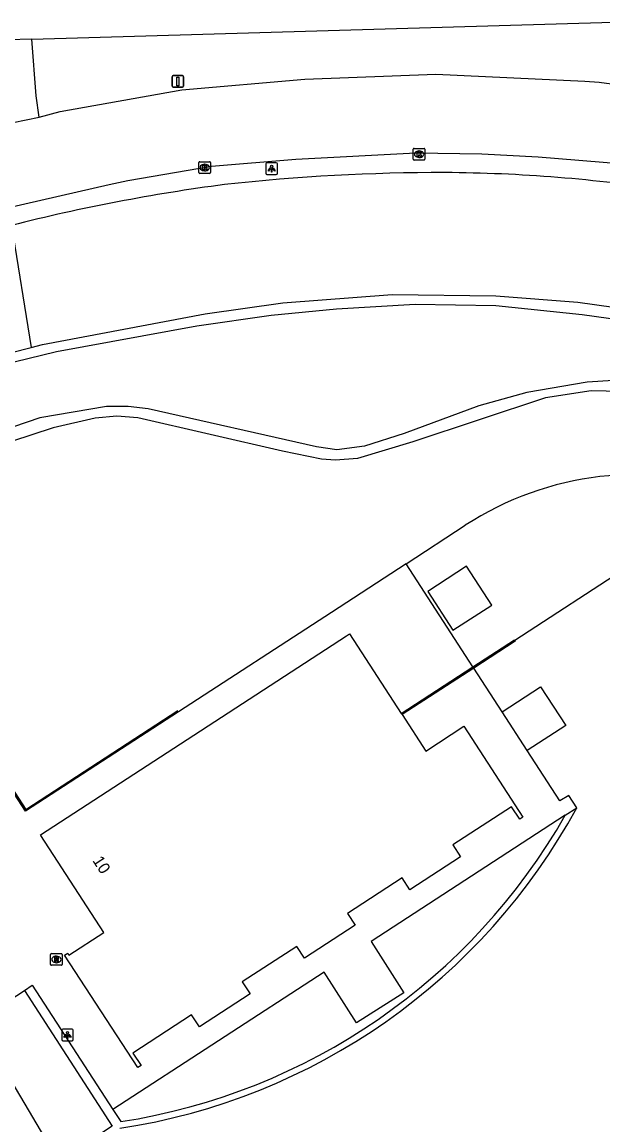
# Model space of a CAD drawing. Extents: x 159451 to 160663, y 388402 to 389723.
# Drawn here: x 160044.7 to 160094.7, y 389283.8 to 389378.7 of the extents above; entities that cross this region are included whole.
import ezdxf

# ---------------------------------------------------------------- set-up
doc = ezdxf.new("R2010")
doc.units = 0
for name, color, linetype in [('IMGEO_Berm_groen', 7, 'Continuous'), ('IMGEO_Groenvoorziening', 7, 'Continuous'), ('IMGEO_Haag', 7, 'Continuous'), ('IMGEO_Kolk', 7, 'Continuous'), ('IMGEO_Lichtpunt', 7, 'Continuous'), ('IMGEO_Loofbos', 7, 'Continuous'), ('IMGEO_Meer_plas_ven_vijver', 7, 'Continuous'), ('IMGEO_Muur', 7, 'Continuous'), ('IMGEO_Open_loods', 7, 'Continuous'), ('IMGEO_Pand', 7, 'Continuous'), ('IMGEO_Pand_nummerreeks', 7, 'Continuous'), ('IMGEO_Parkeervlak_open', 7, 'Continuous'), ('IMGEO_Rijbaan_lokaal_gesloten', 7, 'Continuous'), ('IMGEO_Rijbaan_lokaal_open', 7, 'Continuous'), ('IMGEO_Rioolput', 7, 'Continuous'), ('IMGEO_Verkeersbordpaal', 7, 'Continuous'), ('IMGEO_Voetpad_open', 7, 'Continuous')]:
    doc.layers.add(name, color=color, linetype=linetype)

msp = doc.modelspace()

# ---------------------------------------------------------------- linework, layer by layer
at = {"layer": 'IMGEO_Berm_groen'}
for points in [[(160043.814, 389361.181), (160045.506, 389350.697)], [(160018.398, 389340.073), (160022.188, 389342.228), (160026.213, 389344.023), (160033.578, 389347.076), (160040.631, 389349.447), (160045.506, 389350.697)]]:
    msp.add_lwpolyline(points, dxfattribs=at)
at = {"layer": 'IMGEO_Groenvoorziening'}
for points in [[(160045.569, 389377.185), (160095.565, 389378.647), (160130.286, 389372.303), (160147.497, 389362.17), (160157.284, 389356.446), (160160.932, 389357.287)], [(160045.506, 389350.697), (160046.472, 389350.945), (160060.477, 389353.565), (160067.144, 389354.512), (160076.551, 389355.226), (160085.488, 389355.117), (160092.549, 389354.568), (160100.295, 389353.487), (160106.524, 389352.351), (160119.77, 389349.046), (160128.496, 389345.996), (160138.333, 389341.838), (160146.634, 389337.264), (160151.806, 389333.778), (160161.693, 389326.541), (160174.127, 389316.332), (160188.045, 389305.739), (160195.541, 389299.578), (160199.998, 389295.525), (160201.333, 389293.979), (160202.925, 389291.679)]]:
    msp.add_lwpolyline(points, dxfattribs=at)
at = {"layer": 'IMGEO_Haag'}
msp.add_lwpolyline([(160052.541, 389285.175), (160053.218, 389284.133)], dxfattribs=at)
for centre, radius, start, end in [((160045.066, 389336.905), 53.948, 278.60377, 331.43561), ((160045.068, 389336.904), 53.397, 278.77981, 330.32455)]:
    msp.add_arc(centre, radius, start, end, dxfattribs=at)
at = {"layer": 'IMGEO_Kolk'}
for p, q in [((160078.38, 389366.875), (160078.38, 389367.727)), ((160078.455, 389367.801), (160079.307, 389367.801)), ((160078.868, 389367.581), (160078.893, 389367.581)), ((160079.381, 389367.727), (160079.381, 389366.875)), ((160059.935, 389365.728), (160059.935, 389366.58)), ((160060.01, 389366.654), (160060.862, 389366.654)), ((160060.423, 389366.434), (160060.448, 389366.434)), ((160060.936, 389366.58), (160060.936, 389365.728)), ((160079.307, 389366.801), (160078.455, 389366.801)), ((160078.891, 389367.021), (160078.866, 389367.021)), ((160060.862, 389365.654), (160060.01, 389365.654)), ((160060.446, 389365.874), (160060.421, 389365.874))]:
    msp.add_line(p, q, dxfattribs=at)
for points in [[(160078.38, 389366.875), (160078.38, 389367.727)], [(160078.455, 389367.801), (160079.307, 389367.801)], [(160078.701, 389367.501), (160078.824, 389367.501), (160078.824, 389367.35), (160078.954, 389367.501), (160079.118, 389367.501), (160078.972, 389367.35), (160079.125, 389367.101), (160078.973, 389367.101), (160078.888, 389367.265), (160078.824, 389367.198), (160078.824, 389367.101), (160078.701, 389367.101), (160078.701, 389367.501)], [(160079.381, 389367.727), (160079.381, 389366.875)], [(160059.935, 389365.728), (160059.935, 389366.58)], [(160060.01, 389366.654), (160060.862, 389366.654)], [(160060.256, 389366.354), (160060.379, 389366.354), (160060.379, 389366.203), (160060.509, 389366.354), (160060.673, 389366.354), (160060.527, 389366.203), (160060.68, 389365.954), (160060.528, 389365.954), (160060.443, 389366.118), (160060.379, 389366.051), (160060.379, 389365.954), (160060.256, 389365.954), (160060.256, 389366.354)], [(160060.936, 389366.58), (160060.936, 389365.728)], [(160079.307, 389366.801), (160078.455, 389366.801)], [(160060.862, 389365.654), (160060.01, 389365.654)]]:
    msp.add_lwpolyline(points, dxfattribs=at)
for centre, start, end in [((160078.457, 389367.725), 91.55205, 178.44795), ((160078.457, 389367.725), 91.55205, 178.44795), ((160079.305, 389367.725), 1.55205, 88.44795), ((160079.305, 389367.725), 1.55205, 88.44795), ((160060.012, 389366.578), 91.55205, 178.44795), ((160060.012, 389366.578), 91.55205, 178.44795), ((160060.86, 389366.578), 1.55205, 88.44795), ((160060.86, 389366.578), 1.55205, 88.44795), ((160078.457, 389366.877), 181.55205, 268.44795), ((160078.457, 389366.877), 181.55205, 268.44795), ((160079.305, 389366.877), 271.55205, 358.44795), ((160079.305, 389366.877), 271.55205, 358.44795), ((160060.012, 389365.73), 181.55205, 268.44795), ((160060.012, 389365.73), 181.55205, 268.44795), ((160060.86, 389365.73), 271.55205, 358.44795), ((160060.86, 389365.73), 271.55205, 358.44795)]:
    msp.add_arc(centre, 0.0765, start, end, dxfattribs=at)
for centre, major_axis, ratio, start_param, end_param in [((160078.867, 389367.301), (-0.387, 0.002), 0.722429, 4.712389, 7.853982), ((160078.892, 389367.301), (-0.39, 0.002), 0.717154, 1.570796, 4.712389), ((160060.422, 389366.154), (-0.387, 0.002), 0.722429, 4.712389, 7.853982), ((160060.447, 389366.154), (-0.39, 0.002), 0.717154, 1.570796, 4.712389)]:
    msp.add_ellipse(centre, major_axis=major_axis, ratio=ratio, start_param=start_param, end_param=end_param, dxfattribs=at)
at = {"layer": 'IMGEO_Lichtpunt'}
for p, q in [((160065.697, 389366.469), (160065.697, 389365.662)), ((160065.697, 389366.469), (160065.697, 389365.662)), ((160066.599, 389366.564), (160065.791, 389366.564)), ((160066.599, 389366.564), (160065.791, 389366.564)), ((160066.693, 389365.662), (160066.693, 389366.469)), ((160066.693, 389365.662), (160066.693, 389366.469)), ((160065.791, 389365.568), (160066.599, 389365.568)), ((160065.791, 389365.568), (160066.599, 389365.568)), ((160048.133, 389291.99), (160048.133, 389291.183)), ((160048.133, 389291.99), (160048.133, 389291.183)), ((160049.035, 389292.085), (160048.227, 389292.085)), ((160049.035, 389292.085), (160048.227, 389292.085)), ((160049.129, 389291.183), (160049.129, 389291.99)), ((160049.129, 389291.183), (160049.129, 389291.99)), ((160048.227, 389291.089), (160049.035, 389291.089)), ((160048.227, 389291.089), (160049.035, 389291.089))]:
    msp.add_line(p, q, dxfattribs=at)
for points in [[(160066.071, 389366.133), (160066.11, 389366.105), (160065.922, 389365.843), (160065.884, 389365.87), (160066.071, 389366.133)], [(160066.173, 389366.085), (160066.22, 389366.085), (160066.22, 389365.763), (160066.173, 389365.763), (160066.173, 389366.085)], [(160066.283, 389366.105), (160066.321, 389366.132), (160066.508, 389365.87), (160066.469, 389365.842), (160066.283, 389366.105)], [(160048.507, 389291.654), (160048.546, 389291.626), (160048.358, 389291.364), (160048.32, 389291.391), (160048.507, 389291.654)], [(160048.609, 389291.606), (160048.656, 389291.606), (160048.656, 389291.284), (160048.609, 389291.284), (160048.609, 389291.606)], [(160048.719, 389291.626), (160048.757, 389291.653), (160048.944, 389291.391), (160048.905, 389291.363), (160048.719, 389291.626)]]:
    msp.add_lwpolyline(points, dxfattribs=at)
for centre in [(160066.196, 389366.267), (160048.632, 389291.788)]:
    msp.add_circle(centre, 0.0994, dxfattribs=at)
for centre, start, end in [((160065.791, 389366.469), 90, 180), ((160065.791, 389366.469), 90, 180), ((160066.599, 389366.469), 0, 90), ((160066.599, 389366.469), 0, 90), ((160065.791, 389365.662), 180, 270), ((160065.791, 389365.662), 180, 270), ((160066.599, 389365.662), 270, 0), ((160066.599, 389365.662), 270, 360), ((160048.227, 389291.99), 90, 180), ((160048.227, 389291.99), 90, 180), ((160049.035, 389291.99), 0, 90), ((160049.035, 389291.99), 0, 90), ((160048.227, 389291.183), 180, 270), ((160048.227, 389291.183), 180, 270), ((160049.035, 389291.183), 270, 0), ((160049.035, 389291.183), 270, 360)]:
    msp.add_arc(centre, 0.0946, start, end, dxfattribs=at)
at = {"layer": 'IMGEO_Loofbos'}
for points in [[(160098.863, 389346.856), (160093.685, 389346.964), (160089.754, 389346.344), (160078.338, 389342.571), (160073.595, 389341.144), (160071.698, 389340.985), (160070.477, 389341.073), (160067.132, 389341.758), (160054.691, 389344.631), (160052.871, 389344.773), (160051.013, 389344.594), (160047.404, 389343.778), (160042.037, 389342.015), (160039.755, 389341.385), (160037.8, 389340.373), (160032.743, 389337.955), (160031.499, 389337.656), (160029.543, 389336.58)], [(160106.682, 389338.212), (160087.109, 389325.496)], [(160077.759, 389332.086), (160082.857, 389335.398)]]:
    msp.add_lwpolyline(points, dxfattribs=at)
msp.add_arc((160097.62, 389312.672), 27.1, 70.46406, 123.00807, dxfattribs=at)
at = {"layer": 'IMGEO_Meer_plas_ven_vijver'}
for points in [[(160044.049, 389349.441), (160047.698, 389350.338), (160059.748, 389352.538), (160066.156, 389353.462), (160071.767, 389353.999), (160078.538, 389354.407), (160085.475, 389354.297), (160092.919, 389353.533), (160100.926, 389352.394)], [(160095.595, 389347.843), (160093.338, 389347.7), (160088.149, 389346.808), (160084.023, 389345.667), (160077.591, 389343.283), (160074.184, 389342.209), (160071.809, 389341.886), (160070.066, 389342.148), (160055.562, 389345.42), (160053.841, 389345.622), (160051.983, 389345.603), (160046.256, 389344.646), (160033.801, 389340.408)]]:
    msp.add_lwpolyline(points, dxfattribs=at)
at = {"layer": 'IMGEO_Muur'}
for points in [[(160045.569, 389377.185), (160095.565, 389378.647), (160130.286, 389372.303), (160147.497, 389362.17)], [(160030.791, 389332.74), (160030.585, 389333.058), (160030.677, 389333.118), (160045.043, 389310.963), (160058.127, 389319.463)], [(160058.187, 389319.371), (160045.011, 389310.811), (160030.791, 389332.74)], [(160083.51, 389323.23), (160087.076, 389325.546), (160087.109, 389325.496)], [(160087.109, 389325.496), (160087.142, 389325.446), (160083.577, 389323.13)], [(160077.349, 389319.227), (160083.51, 389323.23)], [(160083.577, 389323.13), (160077.414, 389319.126)]]:
    msp.add_lwpolyline(points, dxfattribs=at)
at = {"layer": 'IMGEO_Open_loods'}
for points in [[(160082.96, 389331.883), (160079.622, 389329.715), (160081.796, 389326.369), (160085.134, 389328.537), (160082.96, 389331.883)], [(160086.018, 389319.373), (160089.327, 389321.523), (160091.495, 389318.186), (160088.186, 389316.036)], [(160088.186, 389316.036), (160086.018, 389319.373)]]:
    msp.add_lwpolyline(points, dxfattribs=at)
at = {"layer": 'IMGEO_Pand'}
for points in [[(160077.414, 389319.126), (160079.452, 389315.99), (160082.735, 389318.123), (160087.818, 389310.299), (160087.544, 389310.121), (160086.841, 389311.203), (160081.785, 389307.918), (160082.449, 389306.895), (160078.089, 389304.062), (160077.424, 389305.085), (160072.728, 389302.035), (160073.393, 389301.011), (160069.032, 389298.179), (160068.368, 389299.202), (160063.672, 389296.151), (160064.336, 389295.128), (160059.976, 389292.295), (160059.311, 389293.318), (160054.254, 389290.033), (160054.957, 389288.951), (160054.697, 389288.782), (160048.365, 389298.443), (160048.648, 389298.628), (160048.76, 389298.456), (160051.754, 389300.401), (160046.335, 389308.742), (160046.306, 389308.786), (160059.497, 389317.356), (160072.645, 389325.898), (160072.905, 389326.067), (160077.349, 389319.227)], [(160077.414, 389319.126), (160077.349, 389319.227)]]:
    msp.add_lwpolyline(points, dxfattribs=at)
at = {"layer": 'IMGEO_Parkeervlak_open'}
msp.add_lwpolyline([(160044.944, 389295.395), (160052.479, 389283.744), (160047.889, 389280.742)], dxfattribs=at)
at = {"layer": 'IMGEO_Rijbaan_lokaal_gesloten'}
for points in [[(160046.187, 389370.471), (160048, 389370.978), (160058.462, 389372.84), (160069.049, 389373.761), (160080.311, 389374.183), (160093.137, 389373.585), (160094.37, 389373.482), (160107.091, 389371.783), (160119.61, 389368.955), (160127.38, 389366.512), (160143.847, 389360.125), (160149.732, 389357.286), (160158.016, 389352.63)], [(160036.109, 389368.424), (160046.187, 389370.471)], [(160096.479, 389366.433), (160089.122, 389367.059), (160084.27, 389367.302), (160078.591, 389367.387), (160068.28, 389366.858), (160061.034, 389366.231), (160053.828, 389365.016), (160052.23, 389364.656), (160043.572, 389362.677), (160040.867, 389362.059), (160032.195, 389359.336), (160018.636, 389353.826), (160016.232, 389352.698), (160010.772, 389350.117), (160007.263, 389348.152)]]:
    msp.add_lwpolyline(points, dxfattribs=at)
at = {"layer": 'IMGEO_Rijbaan_lokaal_open'}
msp.add_lwpolyline([(160047.889, 389280.742), (160040.782, 389292.706)], dxfattribs=at)
at = {"layer": 'IMGEO_Rioolput'}
for p, q in [((160047.179, 389297.647), (160047.179, 389298.499)), ((160047.254, 389298.573), (160048.106, 389298.573)), ((160047.667, 389298.353), (160047.692, 389298.353)), ((160048.18, 389298.499), (160048.18, 389297.647)), ((160048.106, 389297.573), (160047.254, 389297.573)), ((160047.69, 389297.793), (160047.665, 389297.793))]:
    msp.add_line(p, q, dxfattribs=at)
for points in [[(160047.179, 389297.647), (160047.179, 389298.499)], [(160047.254, 389298.573), (160048.106, 389298.573)], [(160047.768, 389298.271), (160047.516, 389298.273), (160047.516, 389297.873)], [(160047.516, 389297.873), (160047.64, 389297.873), (160047.64, 389298.035), (160047.651, 389298.035)], [(160047.694, 389298.192), (160047.64, 389298.192), (160047.64, 389298.111)], [(160047.64, 389298.111), (160047.692, 389298.111)], [(160047.698, 389298.006), (160047.769, 389297.873), (160047.909, 389297.873), (160047.844, 389297.999)], [(160048.18, 389298.499), (160048.18, 389297.647)], [(160048.106, 389297.573), (160047.254, 389297.573)]]:
    msp.add_lwpolyline(points, dxfattribs=at)
for centre, radius, start, end in [((160047.256, 389298.497), 0.0765, 91.55205, 178.44795), ((160047.256, 389298.497), 0.0765, 91.55205, 178.44795), ((160047.65, 389297.982), 0.0533, 26.02933, 88.69889), ((160047.676, 389298.3), 0.19, 274.7715, 282.96867), ((160047.7, 389298.096), 0.0964, 77.00612, 93.18647), ((160047.714, 389298.153), 0.0378, 276.66336, 79.67722), ((160047.767, 389298.161), 0.109, 350.36119, 89.41601), ((160047.765, 389298.161), 0.112, 277.58423, 350.98172), ((160047.749, 389297.946), 0.108, 29.51342, 73.79051), ((160048.104, 389298.497), 0.0765, 1.55205, 88.44795), ((160048.104, 389298.497), 0.0765, 1.55205, 88.44795), ((160047.256, 389297.649), 0.0765, 181.55205, 268.44795), ((160047.256, 389297.649), 0.0765, 181.55205, 268.44795), ((160048.104, 389297.649), 0.0765, 271.55205, 358.44795), ((160048.104, 389297.649), 0.0765, 271.55205, 358.44795)]:
    msp.add_arc(centre, radius, start, end, dxfattribs=at)
for centre, major_axis, ratio, start_param, end_param in [((160047.666, 389298.073), (-0.387, 0.002), 0.722429, 4.712389, 7.853982), ((160047.691, 389298.073), (-0.39, 0.002), 0.717154, 1.570796, 4.712389)]:
    msp.add_ellipse(centre, major_axis=major_axis, ratio=ratio, start_param=start_param, end_param=end_param, dxfattribs=at)
at = {"layer": 'IMGEO_Verkeersbordpaal'}
for p, q in [((160057.632, 389373.159), (160057.632, 389373.959)), ((160057.632, 389373.959), (160057.632, 389373.159)), ((160057.732, 389374.059), (160058.522, 389374.059)), ((160058.522, 389374.059), (160057.732, 389374.059)), ((160058.622, 389373.959), (160058.622, 389373.159)), ((160058.622, 389373.159), (160058.622, 389373.959)), ((160058.522, 389373.059), (160057.732, 389373.059)), ((160057.732, 389373.059), (160058.522, 389373.059))]:
    msp.add_line(p, q, dxfattribs=at)
msp.add_lwpolyline([(160058.052, 389373.934), (160058.202, 389373.934), (160058.202, 389373.184), (160058.052, 389373.184), (160058.052, 389373.934)], dxfattribs=at)
for centre, start, end in [((160057.732, 389373.959), 90, 180), ((160057.732, 389373.959), 90, 180), ((160058.522, 389373.959), 0, 90), ((160058.522, 389373.959), 360, 90), ((160057.732, 389373.159), 180, 270), ((160057.732, 389373.159), 180, 270), ((160058.522, 389373.159), 270, 0), ((160058.522, 389373.159), 270, 0)]:
    msp.add_arc(centre, 0.1, start, end, dxfattribs=at)
at = {"layer": 'IMGEO_Voetpad_open'}
for points in [[(160045.569, 389377.185), (160043.519, 389377.125), (160039.736, 389411.806), (160032.852, 389484.657), (160029.003, 389484.377), (160030.407, 389470.425), (160038.576, 389384.307), (160039.49, 389376.111)], [(160046.187, 389370.471), (160045.926, 389372.321), (160045.569, 389377.185)], [(160077.759, 389332.086), (160071.336, 389327.913), (160058.187, 389319.371), (160045.011, 389310.811), (160030.791, 389332.74), (160030.037, 389332.253)], [(160083.51, 389323.23), (160077.759, 389332.086)], [(160086.018, 389319.373), (160083.577, 389323.13)], [(160092.448, 389311.11), (160091.766, 389312.176), (160091, 389311.703), (160088.186, 389316.036)], [(160091.461, 389310.468), (160074.771, 389299.621), (160077.556, 389295.203), (160073.491, 389292.638), (160070.726, 389296.993), (160052.541, 389285.175)], [(160091.461, 389310.468), (160092.448, 389311.11)], [(160040.782, 389292.706), (160044.944, 389295.395)], [(160044.944, 389295.395), (160045.604, 389295.86), (160052.541, 389285.175)]]:
    msp.add_lwpolyline(points, dxfattribs=at)
for centre, radius, start, end in [((160080.948, 389193.325), 172.394, 89.94789, 96.26042), ((160080.265, 389233.454), 132.268, 81.21797, 89.63607), ((160083.127, 389205.465), 160.602, 97.50559, 104.16925)]:
    msp.add_arc(centre, radius, start, end, dxfattribs=at)

# ---------------------------------------------------------------- texts
at = {"layer": 'IMGEO_Pand_nummerreeks'}
msp.add_text('10', height=1, rotation=303.00963, dxfattribs=at).set_placement((160050.746, 389306.578))

doc.saveas('drawing.dxf')
